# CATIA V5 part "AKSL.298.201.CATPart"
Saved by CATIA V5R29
Part number: АКСЛ.298.021
Definition: Перемычка
Publications: "Грань по длине шипа", "Грань по ширине шипа"
Bounding box of the stored display mesh (mm): x 50 to 227.673, y -233.378 to -50, z 39 to 42
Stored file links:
  Z:\ООО Аксель\Соединения бруса\Соединения бруса\ДУО\AKSL.298.201.CATPart
  Z:\ООО Аксель\Соединения бруса\Соединения бруса\Соединения из листа\АКСЛ.298.020 (Дуо)\AKSL.298.020.CATProduct
  Z:\ООО Аксель\Соединения бруса\Соединения бруса\Соединения из листа\АКСЛ.298.020 (Дуо)\AKSL.298.020.Skelet.CATPart
  Z:\#Catalog_GosNIIAS\Holes&Pockets\Part\Соединение шип-паз\Ship-Paz.CATPart
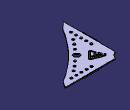
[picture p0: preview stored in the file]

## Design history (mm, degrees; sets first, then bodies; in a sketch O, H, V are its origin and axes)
SheetMetalParameters1: Thickness 3, BendRadius 4, KFactor 0.356492 {= log(min(100,max(20*SheetMetalParameters1.BendRadius,SheetMetalParameters1.Thickness)/SheetMetalParameters1.Thickness))/log(100)/2}, ReliefRadialLength 1, ReliefAxialLength 2, MinimumBendRadius 0
Set1 "Шип в центре грани"
  Extract1 "Плоскость шипа": ExtractElem face of Wall1
  Extract2 "Грань по длине шипа": ExtractElem edge of Extract1
  Extract3 "Грань по ширине шипа": ExtractElem edge of Extract1
Set2
  DatumCurve1: linked copy from another document
  DatumCurve2: linked copy from another document
  Plane1: linked copy from another document
Body1 (main body)
  Pad1: profile DatumCurve2, length 3
  Pocket1: profile DatumCurve1, through (limit type 6)
  Recognize1: Recognize_BendTable SheetMetalParameters1, Recognize_ReferenceFace end face of Pad1, KFacteur 0.356492 {= SheetMetalParameters1.KFactor}, Recognize_BendDefaultRadius 4
  Wall1: Thickness 3, Profile Sketch1, OffsetValue 0
  Sketch1 on face of Recognize1, origin (39, 0, 39), H (0, -1, 0), V (-1, 0, 0)
    reference projected line E1 (52, -188.6727) -> (52, -31.2496) from edge [face of Recognize1 | face of Recognize1]
    line L1 (50, -84.9612) -> (52, -84.9612)
    line L2 (52, -84.9612) -> (52, -134.9612)
    line L3 (52, -134.9612) -> (50, -134.9612)
    line L4 (50, -134.9612) -> (50, -84.9612)
    axis line L5 (52, -109.9612) -> (50, -109.9612)
    point P7 (52, -109.9612)
    point P8 (50, -109.9612)
    distance L2 L4 = 2
    distance L1 L3 = 50
    length E1 = 157.4231 (reference)
    perpendicularity: L2 L1
    midpoint: P7 L2, P8 L4, P7 E1
    coincidence: L2 E1
  SHM_Mirror1: MirroringPlane Plane1, ObjectToMirror Wall1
